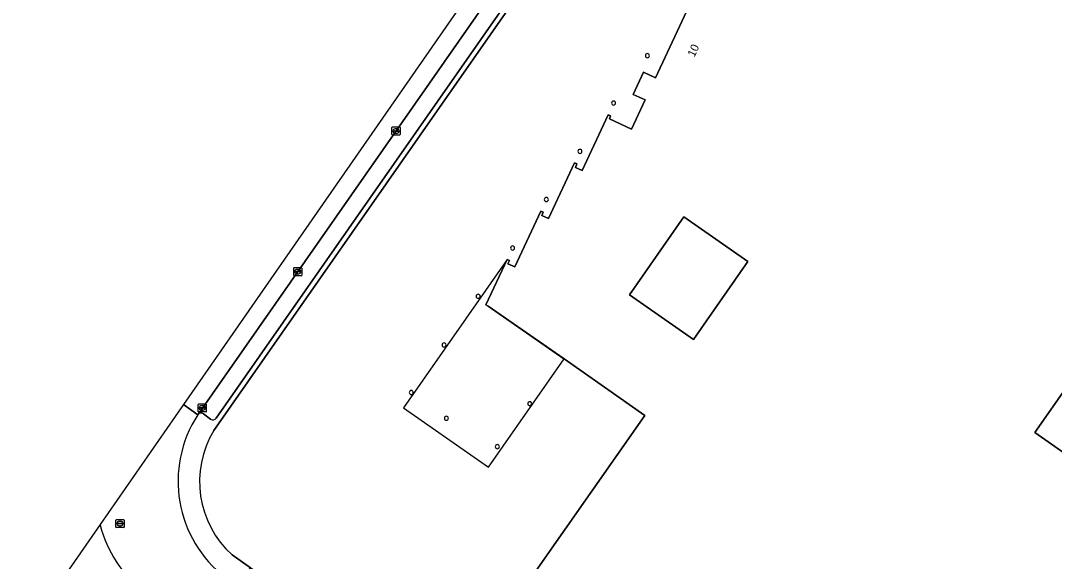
# Model space of a CAD drawing. Extents: x 155018 to 156648, y 383979 to 385733.
# Drawn here: x 155078.5 to 155205.2, y 385014 to 385080.3 of the extents above; entities that cross this region are included whole.
import ezdxf

# ---------------------------------------------------------------- set-up
doc = ezdxf.new("R2010")
doc.units = 0
for name, color, linetype in [('IMGEO_Erf', 7, 'Continuous'), ('IMGEO_Kolk', 7, 'Continuous'), ('IMGEO_Pand', 7, 'Continuous'), ('IMGEO_Pand_nummerreeks', 7, 'Continuous'), ('IMGEO_Pand_overbouw', 7, 'Continuous'), ('IMGEO_Parkeervlak_open', 7, 'Continuous'), ('IMGEO_Rijbaan_lokaal_gesloten', 7, 'Continuous'), ('IMGEO_Rijbaan_lokaal_open', 7, 'Continuous'), ('IMGEO_Rioolput', 7, 'Continuous'), ('IMGEO_Terreindeel_onvherhard', 7, 'Continuous'), ('IMGEO_Voetpad_open', 7, 'Continuous')]:
    doc.layers.add(name, color=color, linetype=linetype)

msp = doc.modelspace()

# ---------------------------------------------------------------- linework, layer by layer
at = {"layer": 'IMGEO_Erf'}
for points in [[(155199.36, 385169.05), (155199.11, 385168.66), (155198.75, 385168.1), (155198.45, 385167.62), (155181.47, 385143.45), (155170.57, 385127.91), (155170.42, 385127.88), (155166.95, 385122.9), (155167.05, 385122.87), (155157.22, 385108.83), (155102.21, 385030.07)], [(155138.55, 385008.43), (155155.03, 385031.91), (155145.13, 385038.83), (155145.1, 385038.85), (155135.81, 385045.29), (155135.55, 385045.47), (155138.14, 385051.02), (155138.44, 385050.89), (155138.25, 385050.46), (155139.1, 385050.1), (155142.29, 385056.94), (155142.58, 385056.81), (155142.39, 385056.38), (155143.23, 385056.01), (155146.41, 385062.85), (155146.7, 385062.71), (155146.51, 385062.29), (155147.36, 385061.9), (155150.54, 385068.74), (155150.83, 385068.6), (155150.68, 385068.23), (155153.39, 385066.98), (155155.08, 385070.56), (155153.61, 385071.23), (155154.88, 385073.97), (155156.33, 385073.27), (155160.73, 385082.7)], [(155223.54, 385059.39), (155202.84, 385029.83), (155219.21, 385018.36)], [(155141.13, 385033.2), (155140.93, 385033.09)], [(155104.46, 385014.82), (155106.7, 385013.25), (155106.73, 385013.22), (155125.6, 385000), (155138.36, 384991.06), (155155.1, 384979.41), (155155.32, 384979.58), (155163.31, 384974.14), (155168.5, 384970.51), (155170.21, 384969.31), (155172.39, 384967.57), (155179.96, 384962.28), (155183.12, 384960.07), (155188.93, 384956.01), (155190.84, 384954.67), (155220.05, 384934.4)]]:
    msp.add_lwpolyline(points, dxfattribs=at)
for centre, radius, start, end in [((155155.34, 385075.97), 0.25, 90, 270), ((155155.34, 385075.97), 0.25, 270, 90), ((155151.19, 385070.17), 0.25, 90, 270), ((155151.19, 385070.17), 0.25, 270, 90), ((155147.07, 385064.25), 0.25, 90, 270), ((155147.07, 385064.25), 0.25, 270, 90), ((155142.95, 385058.35), 0.25, 90, 270), ((155142.95, 385058.35), 0.25, 270, 90), ((155138.81, 385052.41), 0.25, 90, 270), ((155138.81, 385052.41), 0.25, 270, 90), ((155134.6, 385046.5), 0.25, 90, 270), ((155134.6, 385046.5), 0.25, 270, 90), ((155130.42, 385040.54), 0.25, 90, 270), ((155130.42, 385040.54), 0.25, 270, 90), ((155126.39, 385034.71), 0.25, 90, 270), ((155126.39, 385034.71), 0.25, 270, 90), ((155140.93, 385033.34), 0.25, 90, 270), ((155140.93, 385033.34), 0.25, 324.9078, 90.1878), ((155130.7, 385031.56), 0.25, 90, 270), ((155130.7, 385031.56), 0.25, 270, 90), ((155112.47, 385023.79), 12.03, 148.5642, 228.2134), ((155136.94, 385028.08), 0.25, 90, 270), ((155136.94, 385028.08), 0.25, 270, 90)]:
    msp.add_arc(centre, radius, start, end, dxfattribs=at)
at = {"layer": 'IMGEO_Kolk'}
for p, q in [((155124.02, 385066.31), (155124.02, 385067.17)), ((155124.09, 385067.24), (155124.95, 385067.24)), ((155124.28, 385066.73), (155124.28, 385066.75)), ((155124.32, 385066.78), (155124.72, 385066.78)), ((155124.71, 385066.7), (155124.32, 385066.7)), ((155124.51, 385067.02), (155124.53, 385067.02)), ((155124.76, 385066.75), (155124.76, 385066.73)), ((155125.02, 385067.17), (155125.02, 385066.31)), ((155124.95, 385066.24), (155124.09, 385066.24)), ((155124.53, 385066.46), (155124.5, 385066.46)), ((155111.99, 385049.09), (155111.99, 385049.95)), ((155112.06, 385050.02), (155112.91, 385050.02)), ((155112.91, 385049.02), (155112.06, 385049.02)), ((155112.24, 385049.51), (155112.24, 385049.53)), ((155112.68, 385049.48), (155112.28, 385049.48)), ((155112.29, 385049.56), (155112.69, 385049.56)), ((155112.47, 385049.8), (155112.5, 385049.8)), ((155112.5, 385049.24), (155112.47, 385049.24)), ((155112.73, 385049.53), (155112.73, 385049.51)), ((155112.99, 385049.95), (155112.99, 385049.09)), ((155100.27, 385032.4), (155100.27, 385033.25)), ((155100.35, 385033.33), (155101.2, 385033.33)), ((155100.53, 385032.82), (155100.53, 385032.83)), ((155100.57, 385032.87), (155100.97, 385032.87)), ((155100.97, 385032.78), (155100.57, 385032.78)), ((155100.76, 385033.11), (155100.79, 385033.11)), ((155100.78, 385032.55), (155100.76, 385032.55)), ((155101.02, 385032.83), (155101.02, 385032.82)), ((155101.27, 385033.25), (155101.27, 385032.4)), ((155101.2, 385032.33), (155100.35, 385032.33))]:
    msp.add_line(p, q, dxfattribs=at)
for points in [[(155124.02, 385066.31), (155124.02, 385067.17)], [(155124.09, 385067.24), (155124.95, 385067.24)], [(155125.02, 385067.17), (155125.02, 385066.31)], [(155124.95, 385066.24), (155124.09, 385066.24)], [(155111.99, 385049.09), (155111.99, 385049.95)], [(155112.06, 385050.02), (155112.91, 385050.02)], [(155112.91, 385049.02), (155112.06, 385049.02)], [(155112.99, 385049.95), (155112.99, 385049.09)], [(155100.27, 385032.4), (155100.27, 385033.25)], [(155100.35, 385033.33), (155101.2, 385033.33)], [(155101.27, 385033.25), (155101.27, 385032.4)], [(155101.2, 385032.33), (155100.35, 385032.33)]]:
    msp.add_lwpolyline(points, dxfattribs=at)
for centre, radius, start, end in [((155124.09, 385067.16), 0.0765, 91.552, 178.448), ((155124.09, 385067.16), 0.0765, 91.552, 178.448), ((155124.32, 385066.74), 0.0403, 85.8775, 175.7526), ((155124.31, 385066.73), 0.0366, 178.938, 274.7102), ((155124.72, 385066.74), 0.043, 264.8664, 352.4533), ((155124.72, 385066.74), 0.0386, 1.7309, 96.639), ((155124.94, 385067.16), 0.0765, 1.552, 88.448), ((155124.94, 385067.16), 0.0765, 1.552, 88.448), ((155124.09, 385066.32), 0.0765, 181.552, 268.448), ((155124.09, 385066.32), 0.0765, 181.552, 268.448), ((155124.94, 385066.32), 0.0765, 271.552, 358.448), ((155124.94, 385066.32), 0.0765, 271.552, 358.448), ((155112.06, 385049.94), 0.0765, 91.552, 178.448), ((155112.06, 385049.94), 0.0765, 91.552, 178.448), ((155112.06, 385049.09), 0.0765, 181.552, 268.448), ((155112.06, 385049.09), 0.0765, 181.552, 268.448), ((155112.29, 385049.52), 0.0403, 85.8775, 175.7526), ((155112.28, 385049.51), 0.0366, 178.938, 274.7102), ((155112.69, 385049.52), 0.043, 264.8664, 352.4533), ((155112.69, 385049.52), 0.0386, 1.7309, 96.639), ((155112.91, 385049.94), 0.0765, 1.552, 88.448), ((155112.91, 385049.94), 0.0765, 1.552, 88.448), ((155112.91, 385049.09), 0.0765, 271.552, 358.448), ((155112.91, 385049.09), 0.0765, 271.552, 358.448), ((155100.35, 385033.25), 0.0765, 91.552, 178.448), ((155100.35, 385033.25), 0.0765, 91.552, 178.448), ((155100.57, 385032.83), 0.0403, 85.8775, 175.7526), ((155100.57, 385032.82), 0.0366, 178.938, 274.7102), ((155100.98, 385032.83), 0.0386, 1.7309, 96.639), ((155100.97, 385032.83), 0.043, 264.8664, 352.4533), ((155101.2, 385033.25), 0.0765, 1.552, 88.448), ((155101.2, 385033.25), 0.0765, 1.552, 88.448), ((155100.35, 385032.4), 0.0765, 181.552, 268.448), ((155100.35, 385032.4), 0.0765, 181.552, 268.448), ((155101.2, 385032.4), 0.0765, 271.552, 358.448), ((155101.2, 385032.4), 0.0765, 271.552, 358.448)]:
    msp.add_arc(centre, radius, start, end, dxfattribs=at)
for centre, major_axis, ratio, start_param, end_param in [((155124.51, 385066.74), (-0.387, 0.002), 0.722429, 4.712389, 7.853982), ((155124.53, 385066.74), (-0.39, 0.002), 0.717154, 1.570796, 4.712389), ((155112.47, 385049.52), (-0.387, 0.002), 0.722429, 4.712389, 7.853982), ((155112.5, 385049.52), (-0.39, 0.002), 0.717154, 1.570796, 4.712389), ((155100.76, 385032.83), (-0.387, 0.002), 0.722429, 4.712389, 7.853982), ((155100.78, 385032.83), (-0.39, 0.002), 0.717154, 1.570796, 4.712389)]:
    msp.add_ellipse(centre, major_axis=major_axis, ratio=ratio, start_param=start_param, end_param=end_param, dxfattribs=at)
at = {"layer": 'IMGEO_Pand'}
for points in [[(155160.73, 385082.7), (155156.33, 385073.27), (155154.88, 385073.97), (155153.61, 385071.23), (155155.08, 385070.56), (155153.39, 385066.98), (155150.68, 385068.23), (155150.83, 385068.6), (155150.54, 385068.74), (155147.36, 385061.9), (155146.51, 385062.29), (155146.7, 385062.71), (155146.41, 385062.85), (155143.23, 385056.01), (155142.39, 385056.38), (155142.58, 385056.81), (155142.29, 385056.94), (155139.1, 385050.1), (155138.25, 385050.46), (155138.44, 385050.89), (155138.14, 385051.02), (155135.55, 385045.47), (155135.81, 385045.29), (155145.1, 385038.85), (155145.13, 385038.83), (155155.03, 385031.91), (155138.55, 385008.43)], [(155219.21, 385018.36), (155202.84, 385029.83), (155223.54, 385059.39)], [(155140.93, 385033.09), (155141.13, 385033.2)]]:
    msp.add_lwpolyline(points, dxfattribs=at)
msp.add_lwpolyline([(155153.13, 385046.68), (155159.81, 385056.24), (155167.64, 385050.77), (155160.97, 385041.21)], close=True, dxfattribs=at)
for centre, start, end in [((155155.34, 385075.97), 90, 270), ((155155.34, 385075.97), 270, 90), ((155151.19, 385070.17), 90, 270), ((155151.19, 385070.17), 270, 90), ((155147.07, 385064.25), 90, 270), ((155147.07, 385064.25), 270, 90), ((155142.95, 385058.35), 90, 270), ((155142.95, 385058.35), 270, 90), ((155138.81, 385052.41), 90, 270), ((155138.81, 385052.41), 270, 90), ((155134.6, 385046.5), 90, 270), ((155134.6, 385046.5), 270, 90), ((155130.42, 385040.54), 90, 270), ((155130.42, 385040.54), 270, 90), ((155126.39, 385034.71), 90, 270), ((155126.39, 385034.71), 270, 90), ((155140.93, 385033.34), 90, 270), ((155140.93, 385033.34), 324.9078, 90.1878), ((155130.7, 385031.56), 90, 270), ((155130.7, 385031.56), 270, 90), ((155136.94, 385028.08), 90, 270), ((155136.94, 385028.08), 270, 90)]:
    msp.add_arc(centre, 0.25, start, end, dxfattribs=at)
at = {"layer": 'IMGEO_Pand_overbouw'}
msp.add_lwpolyline([(155135.81, 385045.29), (155135.55, 385045.47), (155138.14, 385051.02), (155125.46, 385032.85), (155135.88, 385025.58), (155145.13, 385038.83)], close=True, dxfattribs=at)
at = {"layer": 'IMGEO_Parkeervlak_open'}
for points in [[(155102.48, 385031.58), (155156.74, 385109.21), (155165.88, 385122.21), (155164.16, 385123.4), (155160.52, 385118.21), (155154.95, 385110.29), (155100.24, 385031.99)], [(155100.93, 385032.09), (155101.79, 385031.46)]]:
    msp.add_lwpolyline(points, dxfattribs=at)
for centre, radius, start, end in [((155100.64, 385031.7), 0.493, 53.5186, 143.8991), ((155102.08, 385031.87), 0.499, 234.852, 324.3139)]:
    msp.add_arc(centre, radius, start, end, dxfattribs=at)
at = {"layer": 'IMGEO_Rijbaan_lokaal_gesloten'}
msp.add_lwpolyline([(155098.46, 385033.23), (155100.24, 385031.99), (155154.95, 385110.29), (155160.52, 385118.21), (155164.16, 385123.4), (155168.79, 385130.01), (155172.47, 385135.27), (155186.26, 385155.01), (155195.64, 385168.31), (155194.07, 385169.39), (155193.44, 385169.83)], close=True, dxfattribs=at)
for points in [[(155100.24, 385031.99), (155098.46, 385033.23), (155088.25, 385018.55)], [(155088.25, 385018.55), (155088.27, 385018.46)]]:
    msp.add_lwpolyline(points, dxfattribs=at)
for centre, radius, start, end in [((155112.68, 385023.84), 14.87, 146.7799, 232.6701), ((155102.75, 385022.14), 14.94, 194.2746, 231.6063)]:
    msp.add_arc(centre, radius, start, end, dxfattribs=at)
at = {"layer": 'IMGEO_Rijbaan_lokaal_open'}
msp.add_lwpolyline([(155088.27, 385018.46), (155088.25, 385018.55), (155078.52, 385004.55)], dxfattribs=at)
msp.add_arc((155102.75, 385022.14), 14.94, 194.2746, 231.6063, dxfattribs=at)
at = {"layer": 'IMGEO_Rioolput'}
for p, q in [((155090.2, 385018.23), (155090.2, 385019.08)), ((155090.27, 385019.16), (155091.12, 385019.16)), ((155090.45, 385018.65), (155090.45, 385018.66)), ((155090.89, 385018.61), (155090.49, 385018.61)), ((155090.5, 385018.7), (155090.9, 385018.7)), ((155090.68, 385018.94), (155090.71, 385018.94)), ((155090.94, 385018.66), (155090.94, 385018.65)), ((155091.2, 385019.08), (155091.2, 385018.23)), ((155091.12, 385018.16), (155090.27, 385018.16)), ((155090.71, 385018.38), (155090.68, 385018.38))]:
    msp.add_line(p, q, dxfattribs=at)
for points in [[(155090.2, 385018.23), (155090.2, 385019.08)], [(155090.27, 385019.16), (155091.12, 385019.16)], [(155091.2, 385019.08), (155091.2, 385018.23)], [(155091.12, 385018.16), (155090.27, 385018.16)]]:
    msp.add_lwpolyline(points, dxfattribs=at)
for centre, radius, start, end in [((155090.27, 385019.08), 0.0765, 91.552, 178.448), ((155090.27, 385019.08), 0.0765, 91.552, 178.448), ((155090.5, 385018.66), 0.0403, 85.8775, 175.7526), ((155090.49, 385018.65), 0.0366, 178.938, 274.7102), ((155090.9, 385018.66), 0.043, 264.8664, 352.4533), ((155090.9, 385018.66), 0.0386, 1.7309, 96.639), ((155091.12, 385019.08), 0.0765, 1.552, 88.448), ((155091.12, 385019.08), 0.0765, 1.552, 88.448), ((155090.27, 385018.23), 0.0765, 181.552, 268.448), ((155090.27, 385018.23), 0.0765, 181.552, 268.448), ((155091.12, 385018.23), 0.0765, 271.552, 358.448), ((155091.12, 385018.23), 0.0765, 271.552, 358.448)]:
    msp.add_arc(centre, radius, start, end, dxfattribs=at)
for centre, major_axis, ratio, start_param, end_param in [((155090.68, 385018.66), (-0.387, 0.002), 0.722429, 4.712389, 7.853982), ((155090.71, 385018.66), (-0.39, 0.002), 0.717154, 1.570796, 4.712389)]:
    msp.add_ellipse(centre, major_axis=major_axis, ratio=ratio, start_param=start_param, end_param=end_param, dxfattribs=at)
at = {"layer": 'IMGEO_Terreindeel_onvherhard'}
msp.add_lwpolyline([(155153.13, 385046.68), (155160.97, 385041.21), (155167.64, 385050.77), (155159.81, 385056.24)], close=True, dxfattribs=at)
at = {"layer": 'IMGEO_Voetpad_open'}
for points in [[(155102.21, 385030.07), (155157.22, 385108.83), (155167.05, 385122.87)], [(155166.29, 385122.79), (155165.88, 385122.21), (155156.74, 385109.21), (155102.48, 385031.58)], [(155101.79, 385031.46), (155100.93, 385032.09)], [(155106.34, 385012.72), (155106.7, 385013.25), (155104.46, 385014.82)]]:
    msp.add_lwpolyline(points, dxfattribs=at)
for centre, radius, start, end in [((155112.68, 385023.84), 14.87, 146.7799, 232.6701), ((155100.64, 385031.7), 0.493, 53.5186, 143.8991), ((155102.08, 385031.87), 0.499, 234.852, 324.3139), ((155112.47, 385023.79), 12.03, 148.5642, 228.2134)]:
    msp.add_arc(centre, radius, start, end, dxfattribs=at)

# ---------------------------------------------------------------- texts
at = {"layer": 'IMGEO_Pand_nummerreeks'}
msp.add_text('10', height=1, rotation=64.962, dxfattribs=at).set_placement((155161.1, 385075.73))

doc.saveas('drawing.dxf')
